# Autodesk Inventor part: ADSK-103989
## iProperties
Shininess: 0.0
Created: 2000-11
Part Number: ADSK-103989
Document SubType Name: Modeling
Stock Number: ADSK-103989
Density: 1 g/cm^3
Density: 0.0
Volumn: 0.0
Area: 0.0
PropertySet Name: Model Information
Control State: 0
Master: False
Checked Out: False
Author: gao
